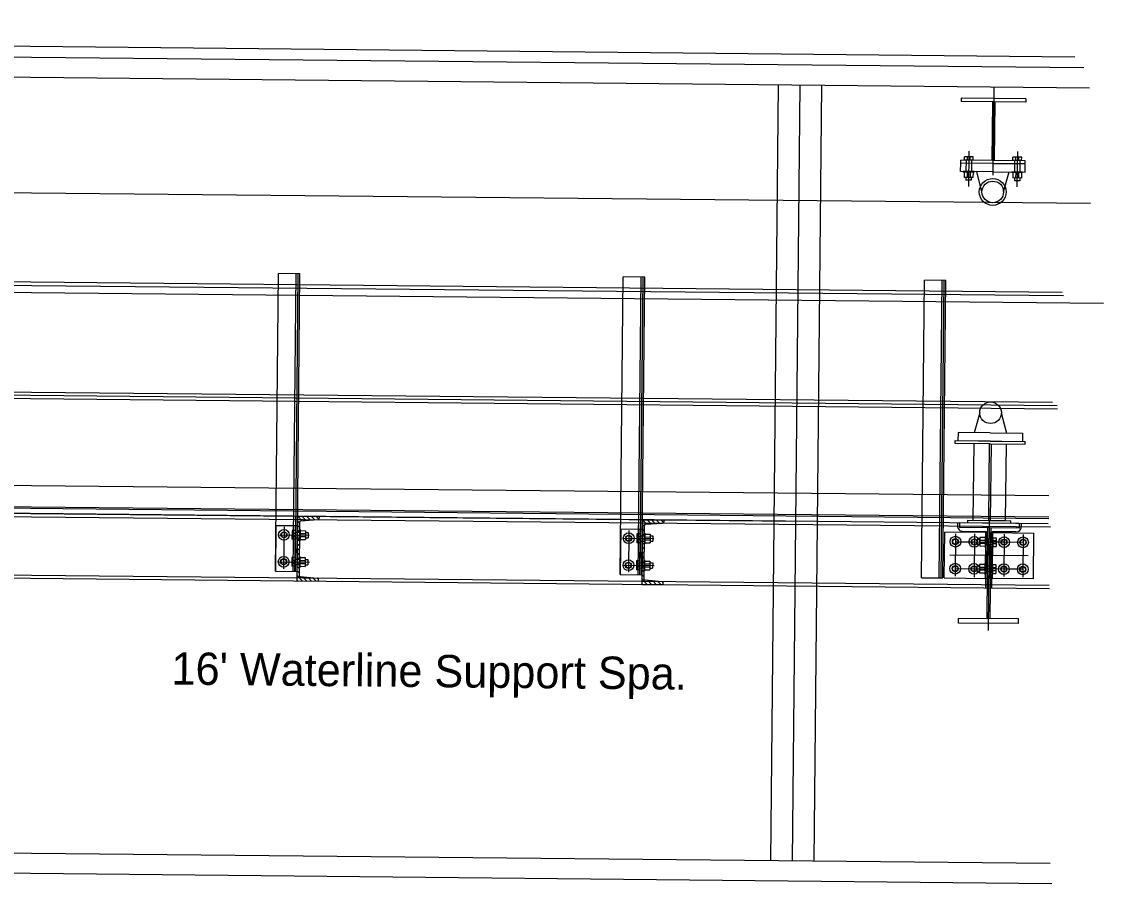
# Model space of a CAD drawing. Extents: x 632312 to 632885, y 378199 to 378534.
# Drawn here: x 632837.06 to 632853.79, y 378357.64 to 378370.97 of the extents above; entities that cross this region are included whole.
import ezdxf

# ---------------------------------------------------------------- set-up
doc = ezdxf.new("R2010")
doc.units = 0
doc.layers.add('SHT_Dimensions', color=7, linetype='Continuous')

msp = doc.modelspace()

# ---------------------------------------------------------------- linework, layer by layer
at = {"layer": 'SHT_Dimensions'}
for p, q in [((632798.767, 378370.974), (632853.347, 378370.431)), ((632798.765, 378370.807), (632853.487, 378370.263)), ((632798.762, 378370.494), (632853.573, 378369.949)), ((632848.76, 378369.997), (632848.641, 378357.998)), ((632849.093, 378369.994), (632848.974, 378357.995)), ((632849.426, 378369.991), (632849.307, 378357.991)), ((632852.093, 378369.963), (632852.079, 378368.599)), ((632851.591, 378369.79), (632851.59, 378369.74)), ((632852.59, 378369.73), (632851.59, 378369.74)), ((632852.591, 378369.78), (632851.591, 378369.79)), ((632852.074, 378369.735), (632852.065, 378368.827)), ((632852.107, 378369.734), (632852.098, 378368.827)), ((632852.591, 378369.78), (632852.59, 378369.73)), ((632851.708, 378368.97), (632851.702, 378368.423)), ((632852.458, 378368.962), (632852.452, 378368.416)), ((632852.581, 378368.822), (632851.581, 378368.832)), ((632851.581, 378368.782), (632851.581, 378368.832)), ((632851.775, 378368.882), (632851.639, 378368.884)), ((632851.639, 378368.832), (632851.639, 378368.884)), ((632851.774, 378368.83), (632851.639, 378368.832)), ((632851.665, 378368.831), (632851.663, 378368.656)), ((632851.684, 378368.831), (632851.684, 378368.883)), ((632851.729, 378368.831), (632851.73, 378368.883)), ((632851.748, 378368.83), (632851.746, 378368.655)), ((632851.774, 378368.83), (632851.775, 378368.882)), ((632852.525, 378368.875), (632852.389, 378368.876)), ((632852.389, 378368.824), (632852.389, 378368.876)), ((632852.524, 378368.823), (632852.389, 378368.824)), ((632852.415, 378368.824), (632852.413, 378368.648)), ((632852.434, 378368.824), (632852.434, 378368.876)), ((632852.479, 378368.823), (632852.479, 378368.875)), ((632852.498, 378368.823), (632852.496, 378368.648)), ((632852.524, 378368.823), (632852.525, 378368.875)), ((632852.581, 378368.772), (632852.581, 378368.822)), ((632853.591, 378368.158), (632798.745, 378368.703)), ((632851.58, 378368.657), (632851.581, 378368.782)), ((632852.08, 378368.652), (632851.58, 378368.657)), ((632852.081, 378368.777), (632851.581, 378368.782)), ((632852.581, 378368.772), (632851.581, 378368.782)), ((632851.621, 378368.656), (632851.621, 378368.646)), ((632851.788, 378368.655), (632851.621, 378368.656)), ((632851.788, 378368.644), (632851.621, 378368.646)), ((632851.637, 378368.646), (632851.636, 378368.562)), ((632851.682, 378368.645), (632851.681, 378368.562)), ((632851.727, 378368.645), (632851.726, 378368.562)), ((632851.772, 378368.644), (632851.771, 378368.561)), ((632851.788, 378368.655), (632851.788, 378368.644)), ((632851.91, 378368.341), (632851.83, 378368.654)), ((632852.08, 378368.652), (632852.58, 378368.647)), ((632852.081, 378368.777), (632852.581, 378368.772)), ((632852.243, 378368.338), (632852.33, 378368.649)), ((632852.371, 378368.649), (632852.371, 378368.638)), ((632852.538, 378368.647), (632852.371, 378368.649)), ((632852.538, 378368.637), (632852.371, 378368.638)), ((632852.387, 378368.638), (632852.386, 378368.555)), ((632852.432, 378368.638), (632852.431, 378368.555)), ((632852.477, 378368.637), (632852.476, 378368.554)), ((632852.522, 378368.637), (632852.521, 378368.554)), ((632852.538, 378368.647), (632852.538, 378368.637)), ((632852.58, 378368.647), (632852.581, 378368.772)), ((632851.771, 378368.561), (632851.636, 378368.562)), ((632851.662, 378368.562), (632851.662, 378368.52)), ((632851.745, 378368.52), (632851.662, 378368.52)), ((632851.745, 378368.561), (632851.745, 378368.52)), ((632852.521, 378368.554), (632852.386, 378368.555)), ((632852.412, 378368.555), (632852.412, 378368.513)), ((632852.495, 378368.512), (632852.412, 378368.513)), ((632852.495, 378368.554), (632852.495, 378368.512)), ((632798.731, 378367.328), (632853.151, 378366.787)), ((632853.788, 378366.614), (632798.729, 378367.161)), ((632798.73, 378367.276), (632853.171, 378366.735)), ((632840.982, 378362.472), (632841.028, 378367.076)), ((632841.361, 378367.073), (632841.028, 378367.076)), ((632841.258, 378362.47), (632841.304, 378367.074)), ((632841.29, 378362.469), (632841.335, 378367.073)), ((632841.316, 378362.469), (632841.361, 378367.073)), ((632846.315, 378362.419), (632846.361, 378367.023)), ((632846.694, 378367.02), (632846.361, 378367.023)), ((632846.591, 378362.417), (632846.637, 378367.021)), ((632846.623, 378362.416), (632846.668, 378367.02)), ((632846.649, 378362.416), (632846.694, 378367.02)), ((632850.974, 378362.371), (632851.02, 378366.975)), ((632851.353, 378366.971), (632851.02, 378366.975)), ((632851.25, 378362.368), (632851.296, 378366.972)), ((632851.281, 378362.368), (632851.327, 378366.972)), ((632851.307, 378362.367), (632851.353, 378366.971)), ((632853, 378365.08), (632798.714, 378365.62)), ((632798.713, 378365.578), (632853.075, 378365.037)), ((632798.713, 378365.526), (632853.08, 378364.985)), ((632851.876, 378364.924), (632851.789, 378364.613)), ((632852.209, 378364.921), (632852.289, 378364.608)), ((632851.54, 378364.615), (632851.538, 378364.49)), ((632852.039, 378364.61), (632851.54, 378364.615)), ((632852.039, 378364.61), (632852.539, 378364.605)), ((632851.496, 378364.449), (632851.497, 378364.491)), ((632852.038, 378364.444), (632851.496, 378364.449)), ((632851.497, 378364.491), (632852.58, 378364.48)), ((632852.038, 378364.485), (632851.538, 378364.49)), ((632851.776, 378363.259), (632851.788, 378364.446)), ((632852.014, 378363.256), (632852.025, 378364.444)), ((632852.038, 378364.485), (632852.538, 378364.48)), ((632852.038, 378364.444), (632852.579, 378364.438)), ((632852.05, 378364.443), (632852.039, 378363.256)), ((632852.539, 378364.605), (632852.538, 378364.48)), ((632852.579, 378364.438), (632852.58, 378364.48)), ((632852.276, 378363.254), (632852.288, 378364.441)), ((632798.7, 378364.182), (632852.946, 378363.643)), ((632798.696, 378363.849), (632852.942, 378363.31)), ((632798.696, 378363.828), (632852.942, 378363.289)), ((632798.695, 378363.745), (632849.026, 378363.244)), ((632852.935, 378363.205), (632836.52, 378363.369)), ((632836.52, 378363.321), (632852.97, 378363.157)), ((632841.324, 378363.321), (632841.314, 378362.321)), ((632841.324, 378363.321), (632841.657, 378363.318)), ((632841.393, 378363.253), (632841.327, 378363.321)), ((632841.359, 378363.321), (632841.359, 378363.319)), ((632841.459, 378363.257), (632841.397, 378363.32)), ((632841.524, 378363.262), (632841.468, 378363.319)), ((632841.59, 378363.267), (632841.539, 378363.319)), ((632841.651, 378363.276), (632841.609, 378363.318)), ((632841.657, 378363.318), (632841.657, 378363.29)), ((632840.989, 378363.181), (632840.982, 378362.472)), ((632840.989, 378363.181), (632841.323, 378363.177)), ((632841.114, 378363.156), (632841.108, 378362.508)), ((632841.284, 378362.469), (632841.291, 378363.178)), ((632841.316, 378362.469), (632841.323, 378363.177)), ((632841.352, 378363.08), (632841.322, 378363.111)), ((632841.354, 378363.221), (632841.323, 378363.253)), ((632841.353, 378363.151), (632841.323, 378363.182)), ((632841.354, 378363.231), (632841.346, 378362.41)), ((632841.353, 378363.115), (632841.351, 378362.948)), ((632841.353, 378363.115), (632841.363, 378363.115)), ((632841.363, 378363.115), (632841.362, 378362.948)), ((632841.375, 378363.252), (632841.636, 378363.27)), ((632846.322, 378363.128), (632846.315, 378362.419)), ((632846.322, 378363.128), (632846.656, 378363.124)), ((632846.617, 378362.416), (632846.624, 378363.125)), ((632846.657, 378363.268), (632846.647, 378362.268)), ((632846.649, 378362.416), (632846.656, 378363.124)), ((632846.687, 378363.168), (632846.656, 378363.2)), ((632846.686, 378363.098), (632846.656, 378363.129)), ((632846.657, 378363.268), (632846.99, 378363.265)), ((632846.726, 378363.2), (632846.66, 378363.268)), ((632846.687, 378363.178), (632846.679, 378362.357)), ((632846.693, 378363.268), (632846.693, 378363.266)), ((632846.708, 378363.199), (632846.969, 378363.217)), ((632846.792, 378363.204), (632846.73, 378363.267)), ((632846.857, 378363.209), (632846.801, 378363.266)), ((632846.923, 378363.214), (632846.872, 378363.266)), ((632846.984, 378363.223), (632846.942, 378363.265)), ((632846.99, 378363.265), (632846.99, 378363.237)), ((632851.532, 378363.219), (632851.531, 378363.171)), ((632851.563, 378363.219), (632851.562, 378363.147)), ((632852.487, 378363.137), (632851.562, 378363.147)), ((632852.488, 378363.21), (632851.563, 378363.219)), ((632851.692, 378363.218), (632851.693, 378363.259)), ((632851.693, 378363.259), (632852.359, 378363.253)), ((632851.776, 378363.259), (632852.276, 378363.254)), ((632851.989, 378361.737), (632852.003, 378363.142)), ((632852.009, 378361.552), (632852.026, 378363.266)), ((632852.047, 378363.142), (632852.033, 378361.737)), ((632852.359, 378363.211), (632852.359, 378363.253)), ((632852.488, 378363.21), (632852.487, 378363.137)), ((632852.519, 378363.21), (632852.519, 378363.162)), ((632841.03, 378363.034), (632841.504, 378363.03)), ((632841.239, 378363.1), (632841.237, 378362.965)), ((632841.289, 378362.964), (632841.237, 378362.965)), ((632841.29, 378363.054), (632841.238, 378363.055)), ((632841.29, 378363.009), (632841.238, 378363.01)), ((632841.291, 378363.1), (632841.239, 378363.1)), ((632841.291, 378363.1), (632841.289, 378362.964)), ((632841.29, 378363.074), (632841.352, 378363.073)), ((632841.29, 378362.99), (632841.352, 378362.99)), ((632841.352, 378363.009), (632841.321, 378363.041)), ((632841.351, 378362.939), (632841.321, 378362.97)), ((632841.351, 378362.948), (632841.362, 378362.948)), ((632841.362, 378363.009), (632841.446, 378363.008)), ((632841.362, 378362.963), (632841.445, 378362.963)), ((632841.363, 378363.099), (632841.446, 378363.098)), ((632841.363, 378363.054), (632841.446, 378363.053)), ((632841.446, 378363.098), (632841.445, 378362.963)), ((632841.445, 378362.989), (632841.487, 378362.988)), ((632841.446, 378363.072), (632841.488, 378363.072)), ((632841.488, 378363.072), (632841.487, 378362.988)), ((632846.363, 378362.981), (632846.837, 378362.977)), ((632846.447, 378363.103), (632846.441, 378362.455)), ((632846.572, 378363.047), (632846.57, 378362.912)), ((632846.623, 378363.001), (632846.571, 378363.002)), ((632846.623, 378362.956), (632846.571, 378362.957)), ((632846.624, 378363.047), (632846.572, 378363.047)), ((632846.624, 378363.047), (632846.622, 378362.911)), ((632846.623, 378363.021), (632846.685, 378363.02)), ((632846.623, 378362.937), (632846.685, 378362.937)), ((632846.685, 378362.956), (632846.654, 378362.987)), ((632846.686, 378363.027), (632846.655, 378363.058)), ((632846.686, 378363.062), (632846.684, 378362.895)), ((632846.686, 378363.062), (632846.696, 378363.061)), ((632846.696, 378363.061), (632846.695, 378362.895)), ((632846.695, 378362.956), (632846.779, 378362.955)), ((632846.696, 378363.046), (632846.779, 378363.045)), ((632846.696, 378363.001), (632846.779, 378363)), ((632846.779, 378363.045), (632846.778, 378362.91)), ((632846.779, 378363.019), (632846.821, 378363.019)), ((632846.821, 378363.019), (632846.82, 378362.935)), ((632851.328, 378362.367), (632851.335, 378363.076)), ((632852.002, 378363.069), (632851.335, 378363.076)), ((632851.502, 378363.051), (632851.495, 378362.397)), ((632851.614, 378363.087), (632851.981, 378363.084)), ((632851.793, 378363.048), (632851.787, 378362.377)), ((632851.834, 378362.966), (632851.833, 378362.883)), ((632851.876, 378362.966), (632851.834, 378362.966)), ((632851.876, 378362.992), (632851.875, 378362.857)), ((632851.959, 378362.991), (632851.876, 378362.992)), ((632851.959, 378362.946), (632851.876, 378362.947)), ((632851.96, 378363.007), (632851.958, 378362.84)), ((632851.97, 378363.007), (632851.96, 378363.007)), ((632851.964, 378362.361), (632851.971, 378363.069)), ((632851.97, 378363.007), (632851.968, 378362.84)), ((632852.077, 378362.964), (632851.97, 378362.965)), ((632851.972, 378362.215), (632851.981, 378363.084)), ((632851.995, 378362.361), (632852.002, 378363.069)), ((632852.039, 378362.36), (632852.046, 378363.068)), ((632852.046, 378363.068), (632852.713, 378363.062)), ((632852.067, 378363.083), (632852.059, 378362.214)), ((632852.435, 378363.079), (632852.067, 378363.083)), ((632852.071, 378362.36), (632852.078, 378363.068)), ((632852.077, 378362.99), (632852.076, 378362.855)), ((632852.076, 378362.945), (632852.129, 378362.944)), ((632852.077, 378362.99), (632852.129, 378362.989)), ((632852.129, 378362.989), (632852.128, 378362.854)), ((632852.255, 378363.043), (632852.248, 378362.387)), ((632852.546, 378363.04), (632852.54, 378362.381)), ((632852.706, 378362.354), (632852.713, 378363.062)), ((632841.35, 378362.797), (632841.319, 378362.828)), ((632841.35, 378362.868), (632841.32, 378362.899)), ((632846.622, 378362.911), (632846.57, 378362.912)), ((632846.683, 378362.744), (632846.652, 378362.775)), ((632846.683, 378362.815), (632846.653, 378362.846)), ((632846.684, 378362.886), (632846.654, 378362.917)), ((632846.684, 378362.895), (632846.695, 378362.895)), ((632846.695, 378362.91), (632846.778, 378362.91)), ((632846.778, 378362.936), (632846.82, 378362.935)), ((632851.5, 378362.928), (632851.792, 378362.925)), ((632851.792, 378362.925), (632852.023, 378362.923)), ((632851.875, 378362.883), (632851.833, 378362.883)), ((632851.959, 378362.901), (632851.875, 378362.902)), ((632851.958, 378362.856), (632851.875, 378362.857)), ((632851.968, 378362.84), (632851.958, 378362.84)), ((632852.076, 378362.881), (632851.969, 378362.882)), ((632852.253, 378362.921), (632852.023, 378362.923)), ((632852.076, 378362.9), (632852.128, 378362.899)), ((632852.076, 378362.855), (632852.128, 378362.854)), ((632852.545, 378362.918), (632852.253, 378362.921)), ((632841.025, 378362.618), (632841.507, 378362.613)), ((632841.234, 378362.683), (632841.233, 378362.548)), ((632841.286, 378362.683), (632841.234, 378362.683)), ((632841.286, 378362.638), (632841.234, 378362.638)), ((632841.286, 378362.683), (632841.285, 378362.548)), ((632841.286, 378362.657), (632841.348, 378362.656)), ((632841.348, 378362.585), (632841.317, 378362.616)), ((632841.349, 378362.727), (632841.318, 378362.758)), ((632841.348, 378362.656), (632841.318, 378362.687)), ((632841.349, 378362.698), (632841.347, 378362.531)), ((632841.349, 378362.698), (632841.359, 378362.698)), ((632841.359, 378362.698), (632841.357, 378362.531)), ((632841.359, 378362.682), (632841.442, 378362.681)), ((632841.359, 378362.637), (632841.442, 378362.636)), ((632841.442, 378362.681), (632841.441, 378362.546)), ((632841.442, 378362.655), (632841.484, 378362.655)), ((632841.484, 378362.655), (632841.483, 378362.572)), ((632846.567, 378362.63), (632846.566, 378362.495)), ((632846.62, 378362.63), (632846.567, 378362.63)), ((632846.62, 378362.63), (632846.618, 378362.495)), ((632846.619, 378362.604), (632846.681, 378362.603)), ((632846.681, 378362.603), (632846.651, 378362.634)), ((632846.682, 378362.674), (632846.652, 378362.705)), ((632846.682, 378362.645), (632846.68, 378362.478)), ((632846.682, 378362.645), (632846.692, 378362.645)), ((632846.692, 378362.645), (632846.691, 378362.478)), ((632846.692, 378362.629), (632846.775, 378362.628)), ((632846.775, 378362.628), (632846.774, 378362.493)), ((632846.775, 378362.602), (632846.817, 378362.602)), ((632852.626, 378362.708), (632851.415, 378362.721)), ((632840.982, 378362.472), (632841.316, 378362.469)), ((632840.982, 378362.472), (632841.316, 378362.469)), ((632841.286, 378362.593), (632841.233, 378362.593)), ((632841.285, 378362.548), (632841.233, 378362.548)), ((632841.285, 378362.574), (632841.347, 378362.573)), ((632841.347, 378362.514), (632841.316, 378362.546)), ((632841.346, 378362.444), (632841.316, 378362.475)), ((632841.347, 378362.531), (632841.357, 378362.531)), ((632841.358, 378362.592), (632841.441, 378362.591)), ((632841.358, 378362.547), (632841.441, 378362.546)), ((632841.441, 378362.572), (632841.483, 378362.572)), ((632846.358, 378362.565), (632846.84, 378362.56)), ((632846.618, 378362.495), (632846.566, 378362.495)), ((632846.619, 378362.585), (632846.567, 378362.585)), ((632846.619, 378362.54), (632846.567, 378362.54)), ((632846.618, 378362.521), (632846.681, 378362.52)), ((632846.68, 378362.461), (632846.649, 378362.493)), ((632846.681, 378362.532), (632846.65, 378362.563)), ((632846.68, 378362.478), (632846.691, 378362.478)), ((632846.691, 378362.539), (632846.774, 378362.538)), ((632846.691, 378362.494), (632846.774, 378362.493)), ((632846.692, 378362.584), (632846.775, 378362.583)), ((632846.774, 378362.519), (632846.816, 378362.519)), ((632846.817, 378362.602), (632846.816, 378362.519)), ((632851.496, 378362.511), (632851.788, 378362.508)), ((632851.788, 378362.508), (632852.019, 378362.506)), ((632851.83, 378362.55), (632851.829, 378362.466)), ((632851.871, 378362.466), (632851.829, 378362.466)), ((632851.872, 378362.549), (632851.83, 378362.55)), ((632851.872, 378362.575), (632851.871, 378362.44)), ((632851.955, 378362.529), (632851.871, 378362.53)), ((632851.954, 378362.484), (632851.871, 378362.485)), ((632851.954, 378362.439), (632851.871, 378362.44)), ((632851.955, 378362.575), (632851.872, 378362.575)), ((632851.955, 378362.59), (632851.954, 378362.423)), ((632851.966, 378362.59), (632851.955, 378362.59)), ((632851.966, 378362.59), (632851.964, 378362.423)), ((632852.073, 378362.547), (632851.965, 378362.548)), ((632852.072, 378362.464), (632851.965, 378362.465)), ((632852.249, 378362.504), (632852.019, 378362.506)), ((632852.073, 378362.573), (632852.071, 378362.438)), ((632852.071, 378362.438), (632852.124, 378362.437)), ((632852.072, 378362.528), (632852.124, 378362.528)), ((632852.072, 378362.483), (632852.124, 378362.483)), ((632852.073, 378362.573), (632852.125, 378362.573)), ((632852.125, 378362.573), (632852.124, 378362.437)), ((632852.541, 378362.501), (632852.249, 378362.504)), ((632836.06, 378362.421), (632852.949, 378362.253)), ((632836.06, 378362.373), (632852.954, 378362.205)), ((632841.327, 378362.321), (632841.314, 378362.333)), ((632841.317, 378362.321), (632841.314, 378362.324)), ((632841.314, 378362.321), (632841.647, 378362.318)), ((632841.314, 378362.321), (632841.647, 378362.318)), ((632841.397, 378362.32), (632841.315, 378362.404)), ((632841.366, 378362.389), (632841.627, 378362.366)), ((632841.468, 378362.319), (632841.403, 378362.386)), ((632841.539, 378362.319), (632841.48, 378362.379)), ((632841.609, 378362.318), (632841.556, 378362.372)), ((632841.647, 378362.351), (632841.634, 378362.365)), ((632841.647, 378362.318), (632841.648, 378362.345)), ((632846.315, 378362.419), (632846.649, 378362.416)), ((632846.315, 378362.419), (632846.649, 378362.416)), ((632846.66, 378362.268), (632846.647, 378362.28)), ((632846.65, 378362.268), (632846.647, 378362.271)), ((632846.647, 378362.268), (632846.98, 378362.265)), ((632846.647, 378362.268), (632846.98, 378362.265)), ((632846.73, 378362.267), (632846.648, 378362.351)), ((632846.679, 378362.391), (632846.649, 378362.422)), ((632846.699, 378362.336), (632846.96, 378362.313)), ((632846.801, 378362.266), (632846.736, 378362.333)), ((632846.872, 378362.266), (632846.813, 378362.326)), ((632846.943, 378362.265), (632846.889, 378362.319)), ((632846.98, 378362.298), (632846.967, 378362.312)), ((632846.98, 378362.265), (632846.981, 378362.292)), ((632850.974, 378362.371), (632851.307, 378362.367)), ((632851.328, 378362.367), (632851.995, 378362.361)), ((632851.964, 378362.423), (632851.954, 378362.423)), ((632852.706, 378362.354), (632852.039, 378362.36)), ((632852.473, 378361.732), (632851.548, 378361.742)), ((632851.548, 378361.669), (632851.548, 378361.742)), ((632852.473, 378361.66), (632851.548, 378361.669)), ((632852.473, 378361.66), (632852.473, 378361.732)), ((632798.643, 378358.495), (632852.964, 378357.955)), ((632798.64, 378358.182), (632852.992, 378357.642))]:
    msp.add_line(p, q, dxfattribs=at)
for centre, radius in [((632852.077, 378368.339), 0.208), ((632852.077, 378368.339), 0.167), ((632852.043, 378364.923), 0.167), ((632841.113, 378363.034), 0.0833), ((632841.113, 378363.034), 0.0469), ((632841.113, 378363.034), 0.0417), ((632846.446, 378362.981), 0.0833), ((632846.446, 378362.981), 0.0469), ((632846.446, 378362.981), 0.0417), ((632851.5, 378362.928), 0.0833), ((632851.5, 378362.928), 0.0469), ((632851.5, 378362.928), 0.0417), ((632851.792, 378362.925), 0.0833), ((632851.792, 378362.925), 0.0469), ((632851.792, 378362.925), 0.0417), ((632852.253, 378362.921), 0.0833), ((632852.253, 378362.921), 0.0469), ((632852.253, 378362.921), 0.0417), ((632852.545, 378362.918), 0.0833), ((632852.545, 378362.918), 0.0469), ((632852.545, 378362.918), 0.0417), ((632841.109, 378362.617), 0.0833), ((632841.109, 378362.617), 0.0469), ((632841.109, 378362.617), 0.0417), ((632846.442, 378362.564), 0.0833), ((632846.442, 378362.564), 0.0469), ((632846.442, 378362.564), 0.0417), ((632851.496, 378362.511), 0.0833), ((632851.496, 378362.511), 0.0469), ((632851.496, 378362.511), 0.0417), ((632851.788, 378362.508), 0.0833), ((632851.788, 378362.508), 0.0469), ((632851.788, 378362.508), 0.0417), ((632852.249, 378362.504), 0.0833), ((632852.249, 378362.504), 0.0469), ((632852.249, 378362.504), 0.0417), ((632852.541, 378362.501), 0.0833), ((632852.541, 378362.501), 0.0469), ((632852.541, 378362.501), 0.0417)]:
    msp.add_circle(centre, radius, dxfattribs=at)
for centre, radius, start, end in [((632841.636, 378363.291), 0.0208, 269.4304, 359.4388), ((632841.375, 378363.231), 0.0208, 89.4304, 179.4304), ((632846.708, 378363.178), 0.0208, 89.4304, 179.4304), ((632846.969, 378363.238), 0.0208, 269.4304, 359.4388), ((632851.615, 378363.171), 0.0833, 179.4304, 269.4304), ((632852.436, 378363.162), 0.0833, 269.4304, 359.4304), ((632841.367, 378362.41), 0.0208, 179.4304, 269.4304), ((632841.627, 378362.345), 0.0208, 359.4304, 89.4304), ((632846.7, 378362.357), 0.0208, 179.4304, 269.4304), ((632846.96, 378362.292), 0.0208, 359.4304, 89.4304)]:
    msp.add_arc(centre, radius, start, end, dxfattribs=at)

# ---------------------------------------------------------------- texts
msp.add_text("16' Waterline Support Spa.", height=0.5, rotation=359.4304, dxfattribs=at).set_placement((632839.372, 378360.718))

doc.saveas('drawing.dxf')
